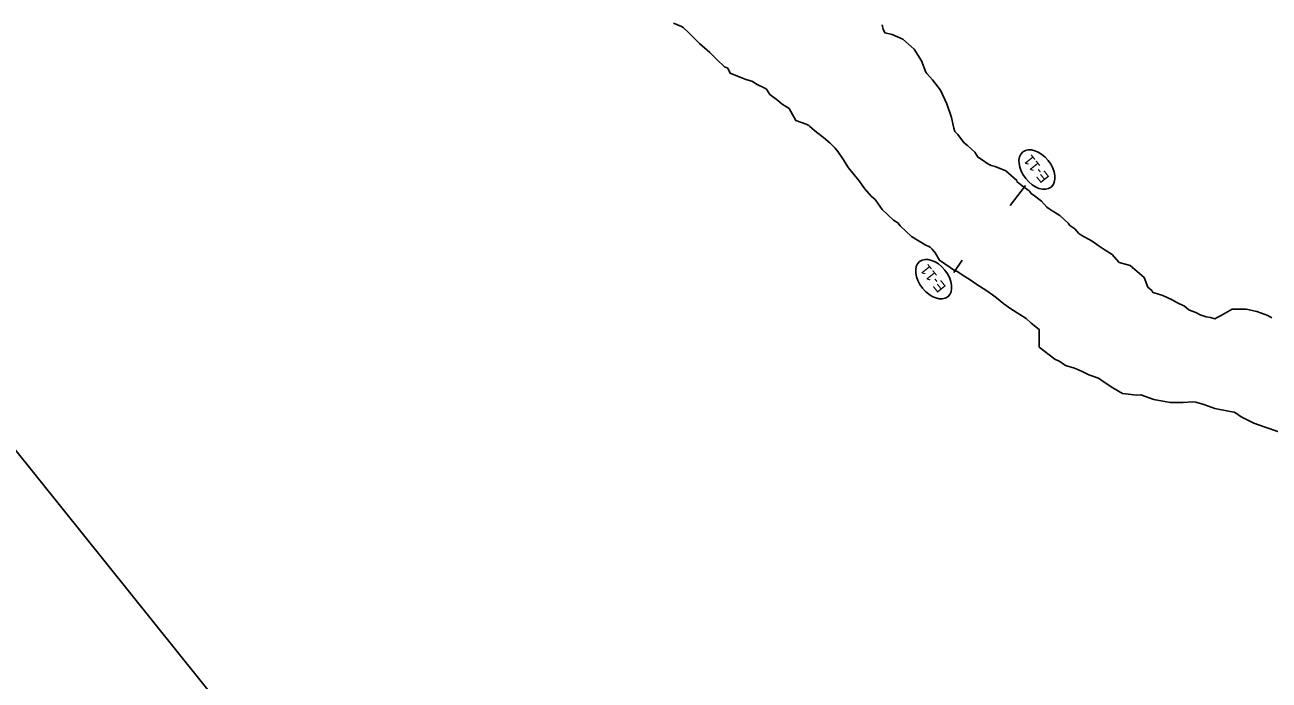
# Model space of a CAD drawing. Extents: x 641687 to 655797, y 406445 to 431088.
# Drawn here: x 650452 to 651614, y 415670 to 416282 of the extents above; entities that cross this region are included whole.
import ezdxf

# ---------------------------------------------------------------- set-up
doc = ezdxf.new("R2010")
doc.units = 0
for name, color, linetype in [('R_Erosion', 7, 'Continuous'), ('R_Erosion_Buffer', 7, 'Continuous'), ('R_Erosion_Silt Fence', 7, 'Continuous'), ('R_No Plot', 7, 'Continuous')]:
    doc.layers.add(name, color=color, linetype=linetype)

msp = doc.modelspace()

# ---------------------------------------------------------------- linework, layer by layer
at = {"layer": 'R_Erosion'}
for centre in [(651397.4, 416146.9), (651300.9, 416044.5)]:
    msp.add_ellipse(centre, major_axis=(-13.2, 16.4), ratio=0.638788, dxfattribs=at)
at = {"layer": 'R_Erosion_Buffer'}
for points in [[(651623.6, 415901.7), (651609.7, 415906.4), (651600, 415909.9), (651588.3, 415915.9), (651582.9, 415919.7), (651581.8, 415920.1), (651581.6, 415920.2), (651578.1, 415920.7), (651563.7, 415923.6), (651553.4, 415927.4), (651546, 415929.6), (651543.1, 415929.8), (651534.2, 415929.1), (651521.9, 415929.3), (651506.7, 415932.1), (651494.5, 415936.3), (651494.4, 415936.4), (651490.8, 415936), (651477.4, 415937.6), (651468.3, 415943.1), (651460.4, 415948.3), (651455.1, 415951.9), (651445.9, 415955.1), (651439, 415958.6), (651432.6, 415961.3), (651424, 415963.8), (651418.7, 415967.6), (651414.1, 415969.7), (651399.4, 415981), (651399.4, 415997.5), (651391.9, 416003.5), (651387.5, 416007.8), (651381.3, 416011.6), (651373.1, 416016.7), (651366.4, 416021.3), (651359.5, 416026.9), (651356, 416029.8), (651349.6, 416034.2), (651341.2, 416039.4), (651335, 416043.8), (651328.5, 416048), (651322.5, 416052.1), (651321.4, 416052.1), (651306.4, 416062.2), (651302.4, 416069.2), (651299.4, 416072.5), (651297.7, 416074.3), (651297.1, 416074.8), (651292.8, 416076.5), (651280.1, 416084.3), (651269.6, 416094.4), (651267.5, 416097.2), (651263.5, 416099.7), (651252.9, 416109.6), (651246.1, 416119), (651242.5, 416121.9), (651236.1, 416129.2), (651231.3, 416136.5), (651226.7, 416141.9), (651221.4, 416148.6), (651216.1, 416157), (651211.4, 416163.7), (651208.5, 416167.3), (651204.1, 416171.4), (651197.8, 416176.8), (651191.5, 416181.8), (651185.1, 416187.2), (651184.2, 416187.9), (651181.8, 416189.2), (651172, 416192.8), (651165.7, 416203.9), (651159.3, 416207.9), (651154.8, 416211.8), (651147.8, 416217.1), (651144.6, 416221.9), (651142.5, 416223.2), (651135.8, 416226.5), (651131.7, 416229.3), (651131.2, 416229.6), (651131.1, 416229.6), (651125.3, 416230.9), (651110.7, 416237), (651108.5, 416241.7), (651105.4, 416243), (651098.1, 416249.8), (651091.8, 416256.3), (651082.2, 416264.6), (651071.9, 416275.1), (651066.8, 416279.7), (651065.3, 416280.5), (651057.9, 416283.6)], [(651623.6, 415901.7), (651609.7, 415906.4), (651600, 415909.9), (651588.3, 415915.9), (651582.9, 415919.7), (651581.8, 415920.1), (651581.6, 415920.2), (651578.1, 415920.7), (651563.7, 415923.6), (651553.4, 415927.4), (651546, 415929.6), (651543.1, 415929.8), (651534.2, 415929.1), (651521.9, 415929.3), (651506.7, 415932.1), (651494.5, 415936.3), (651494.4, 415936.4), (651490.8, 415936), (651477.4, 415937.6), (651468.3, 415943.1), (651460.4, 415948.3), (651455.1, 415951.9), (651445.9, 415955.1), (651439, 415958.6), (651432.6, 415961.3), (651424, 415963.8), (651418.7, 415967.6), (651414.1, 415969.7), (651399.4, 415981), (651399.4, 415997.5), (651391.9, 416003.5), (651387.5, 416007.8), (651381.3, 416011.6), (651373.1, 416016.7), (651366.4, 416021.3), (651359.5, 416026.9), (651356, 416029.8), (651349.6, 416034.2), (651341.2, 416039.4), (651335, 416043.8), (651328.5, 416048), (651322.5, 416052.1), (651321.4, 416052.1), (651306.4, 416062.2), (651302.4, 416069.2), (651299.4, 416072.5), (651297.7, 416074.3), (651297.1, 416074.8), (651292.8, 416076.5), (651280.1, 416084.3), (651269.6, 416094.4), (651267.5, 416097.2), (651263.5, 416099.7), (651252.9, 416109.6), (651246.1, 416119), (651242.5, 416121.9), (651236.1, 416129.2), (651231.3, 416136.5), (651226.7, 416141.9), (651221.4, 416148.6), (651216.1, 416157), (651211.4, 416163.7), (651208.5, 416167.3), (651204.1, 416171.4), (651197.8, 416176.8), (651191.5, 416181.8), (651185.1, 416187.2), (651184.2, 416187.9), (651181.8, 416189.2), (651172, 416192.8), (651165.7, 416203.9), (651159.3, 416207.9), (651154.8, 416211.8), (651147.8, 416217.1), (651144.6, 416221.9), (651142.5, 416223.2), (651135.8, 416226.5), (651131.7, 416229.3), (651131.2, 416229.6), (651131.1, 416229.6), (651125.3, 416230.9), (651110.7, 416237), (651108.5, 416241.7), (651105.4, 416243), (651098.1, 416249.8), (651091.8, 416256.3), (651082.2, 416264.6), (651071.9, 416275.1), (651066.8, 416279.7), (651065.3, 416280.5), (651057.9, 416283.6)], [(651623.6, 415901.7), (651609.7, 415906.4), (651600, 415909.9), (651588.3, 415915.9), (651582.9, 415919.7), (651581.8, 415920.1), (651581.6, 415920.2), (651578.1, 415920.7), (651563.7, 415923.6), (651553.4, 415927.4), (651546, 415929.6), (651543.1, 415929.8), (651534.2, 415929.1), (651521.9, 415929.3), (651506.7, 415932.1), (651494.5, 415936.3), (651494.4, 415936.4), (651490.8, 415936), (651477.4, 415937.6), (651468.3, 415943.1), (651460.4, 415948.3), (651455.1, 415951.9), (651445.9, 415955.1), (651439, 415958.6), (651432.6, 415961.3), (651424, 415963.8), (651418.7, 415967.6), (651414.1, 415969.7), (651399.4, 415981), (651399.4, 415997.5), (651391.9, 416003.5), (651387.5, 416007.8), (651381.3, 416011.6), (651373.1, 416016.7), (651366.4, 416021.3), (651359.5, 416026.9), (651356, 416029.8), (651349.6, 416034.2), (651341.2, 416039.4), (651335, 416043.8), (651328.5, 416048), (651322.5, 416052.1), (651321.4, 416052.1), (651306.4, 416062.2), (651302.4, 416069.2), (651299.4, 416072.5), (651297.7, 416074.3), (651297.1, 416074.8), (651292.8, 416076.5), (651280.1, 416084.3), (651269.6, 416094.4), (651267.5, 416097.2), (651263.5, 416099.7), (651252.9, 416109.6), (651246.1, 416119), (651242.5, 416121.9), (651236.1, 416129.2), (651231.3, 416136.5), (651226.7, 416141.9), (651221.4, 416148.6), (651216.1, 416157), (651211.4, 416163.7), (651208.5, 416167.3), (651204.1, 416171.4), (651197.8, 416176.8), (651191.5, 416181.8), (651185.1, 416187.2), (651184.2, 416187.9), (651181.8, 416189.2), (651172, 416192.8), (651165.7, 416203.9), (651159.3, 416207.9), (651154.8, 416211.8), (651147.8, 416217.1), (651144.6, 416221.9), (651142.5, 416223.2), (651135.8, 416226.5), (651131.7, 416229.3), (651131.2, 416229.6), (651131.1, 416229.6), (651125.3, 416230.9), (651110.7, 416237), (651108.5, 416241.7), (651105.4, 416243), (651098.1, 416249.8), (651091.8, 416256.3), (651082.2, 416264.6), (651071.9, 416275.1), (651066.8, 416279.7), (651065.3, 416280.5), (651057.9, 416283.6)], [(651252.7, 416282.1), (651253.7, 416277.7), (651254.8, 416275.6), (651255.3, 416274.5), (651262.2, 416273), (651272, 416268.8), (651282.6, 416259.4), (651289.4, 416248.6), (651293.7, 416238), (651294.5, 416236.7), (651299.9, 416230.8), (651307.4, 416221.1), (651313.1, 416208.4), (651317.6, 416195.5), (651319.9, 416185.5), (651320.6, 416182.5), (651323.4, 416179.5), (651327.7, 416173.8), (651329.8, 416171.5), (651332.6, 416169.3), (651339.3, 416163.1), (651342.6, 416158.1), (651342.7, 416158.1), (651346.3, 416156.1), (651351.4, 416152.3), (651354.6, 416150.8), (651358.5, 416149.7), (651368.2, 416145.7), (651378.5, 416136.6), (651378.9, 416135.4), (651383.5, 416131.8), (651390.1, 416127), (651392.3, 416124.1), (651394, 416123.3), (651401.8, 416117.5), (651406.7, 416111.8), (651409.7, 416109.7), (651418.8, 416103.9), (651426.5, 416096.9), (651428.3, 416094.6), (651432.8, 416091.4), (651436.7, 416087.1), (651439.5, 416085.3), (651449.1, 416080), (651455.5, 416075.2), (651460.3, 416072.3), (651467.6, 416067.6), (651474.1, 416060.3), (651474.4, 416059.9), (651484.6, 416057.4), (651497.6, 416046.1), (651501, 416037.1), (651504.7, 416033.9), (651505.8, 416032), (651507, 416031.6), (651515.1, 416029.2), (651523.8, 416025.3), (651528.2, 416022.8), (651535.4, 416019.4), (651539.5, 416015.8), (651540.1, 416015.4), (651546, 416013.3), (651550, 416011.2), (651552.9, 416010.1), (651555.7, 416009.3), (651559.6, 416008.6), (651563.7, 416007.3), (651565.8, 416008.6), (651568.9, 416010.3), (651579.9, 416016.3), (651593, 416016.3), (651603, 416014.4), (651613.3, 416010.4), (651616.8, 416008.2)], [(651252.7, 416282.1), (651253.7, 416277.7), (651254.8, 416275.6), (651255.3, 416274.5), (651262.2, 416273), (651272, 416268.8), (651282.6, 416259.4), (651289.4, 416248.6), (651293.7, 416238), (651294.5, 416236.7), (651299.9, 416230.8), (651307.4, 416221.1), (651313.1, 416208.4), (651317.6, 416195.5), (651319.9, 416185.5), (651320.6, 416182.5), (651323.4, 416179.5), (651327.7, 416173.8), (651329.8, 416171.5), (651332.6, 416169.3), (651339.3, 416163.1), (651342.6, 416158.1), (651342.7, 416158.1), (651346.3, 416156.1), (651351.4, 416152.3), (651354.6, 416150.8), (651358.5, 416149.7), (651368.2, 416145.7), (651378.5, 416136.6), (651378.9, 416135.4), (651383.5, 416131.8), (651390.1, 416127), (651392.3, 416124.1), (651394, 416123.3), (651401.8, 416117.5), (651406.7, 416111.8), (651409.7, 416109.7), (651418.8, 416103.9), (651426.5, 416096.9), (651428.3, 416094.6), (651432.8, 416091.4), (651436.7, 416087.1), (651439.5, 416085.3), (651449.1, 416080), (651455.5, 416075.2), (651460.3, 416072.3), (651467.6, 416067.6), (651474.1, 416060.3), (651474.4, 416059.9), (651484.6, 416057.4), (651497.6, 416046.1), (651501, 416037.1), (651504.7, 416033.9), (651505.8, 416032), (651507, 416031.6), (651515.1, 416029.2), (651523.8, 416025.3), (651528.2, 416022.8), (651535.4, 416019.4), (651539.5, 416015.8), (651540.1, 416015.4), (651546, 416013.3), (651550, 416011.2), (651552.9, 416010.1), (651555.7, 416009.3), (651559.6, 416008.6), (651563.7, 416007.3), (651565.8, 416008.6), (651568.9, 416010.3), (651579.9, 416016.3), (651593, 416016.3), (651603, 416014.4), (651613.3, 416010.4), (651616.8, 416008.2)], [(651252.7, 416282.1), (651253.7, 416277.7), (651254.8, 416275.6), (651255.3, 416274.5), (651262.2, 416273), (651272, 416268.8), (651282.6, 416259.4), (651289.4, 416248.6), (651293.7, 416238), (651294.5, 416236.7), (651299.9, 416230.8), (651307.4, 416221.1), (651313.1, 416208.4), (651317.6, 416195.5), (651319.9, 416185.5), (651320.6, 416182.5), (651323.4, 416179.5), (651327.7, 416173.8), (651329.8, 416171.5), (651332.6, 416169.3), (651339.3, 416163.1), (651342.6, 416158.1), (651342.7, 416158.1), (651346.3, 416156.1), (651351.4, 416152.3), (651354.6, 416150.8), (651358.5, 416149.7), (651368.2, 416145.7), (651378.5, 416136.6), (651378.9, 416135.4), (651383.5, 416131.8), (651390.1, 416127), (651392.3, 416124.1), (651394, 416123.3), (651401.8, 416117.5), (651406.7, 416111.8), (651409.7, 416109.7), (651418.8, 416103.9), (651426.5, 416096.9), (651428.3, 416094.6), (651432.8, 416091.4), (651436.7, 416087.1), (651439.5, 416085.3), (651449.1, 416080), (651455.5, 416075.2), (651460.3, 416072.3), (651467.6, 416067.6), (651474.1, 416060.3), (651474.4, 416059.9), (651484.6, 416057.4), (651497.6, 416046.1), (651501, 416037.1), (651504.7, 416033.9), (651505.8, 416032), (651507, 416031.6), (651515.1, 416029.2), (651523.8, 416025.3), (651528.2, 416022.8), (651535.4, 416019.4), (651539.5, 416015.8), (651540.1, 416015.4), (651546, 416013.3), (651550, 416011.2), (651552.9, 416010.1), (651555.7, 416009.3), (651559.6, 416008.6), (651563.7, 416007.3), (651565.8, 416008.6), (651568.9, 416010.3), (651579.9, 416016.3), (651593, 416016.3), (651603, 416014.4), (651613.3, 416010.4), (651616.8, 416008.2)]]:
    msp.add_lwpolyline(points, dxfattribs=at)
at = {"layer": 'R_Erosion_Silt Fence'}
for p, q in [((651372.3, 416113.4), (651386.7, 416132)), ((651327.4, 416062.2), (651319.7, 416050.8))]:
    msp.add_line(p, q, dxfattribs=at)
at = {"layer": 'R_No Plot'}
msp.add_lwpolyline([(651236.9, 418130.7), (649657.6, 416863), (649657.6, 416863), (651159.9, 414991.3), (652739.3, 416259)], close=True, dxfattribs=at)

# ---------------------------------------------------------------- texts
at = {"layer": 'R_Erosion'}
for p in [(651409.6, 416139.6), (651313, 416037.2)]:
    msp.add_text('E-11', height=10, rotation=128.7535, dxfattribs=at).set_placement(p)

doc.saveas('drawing.dxf')
